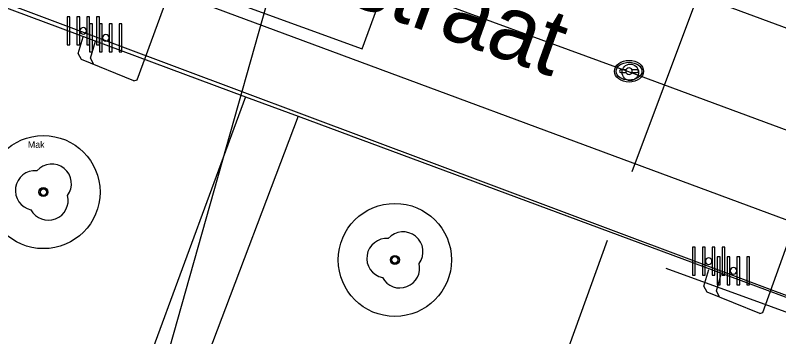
# Model space of a CAD drawing. Extents: x 192672 to 192910, y 446344 to 446512.
# Drawn here: x 192773.19 to 192796.29, y 446370.4 to 446380.14 of the extents above; entities that cross this region are included whole.
import ezdxf

# ---------------------------------------------------------------- set-up
doc = ezdxf.new("R2010")
doc.units = 0
for name, color, linetype in [('B-GV-GR-BOOM-S', 7, 'Continuous'), ('B-OI-KL-()_OVERIG_RIOOLVRIJVERVAL-S', 7, 'Continuous'), ('B-OI-KL-DATA_KABELBED-G', 7, 'Continuous'), ('B-OI-KL-ET_LS-G', 7, 'Continuous'), ('B-OI-RI-RIOOLVRIJVERVAL-G', 7, 'Continuous'), ('boom', 7, 'Continuous'), ('Default', 7, 'Continuous'), ('inspectie-   rioolput', 7, 'Continuous'), ('kant open verharding', 7, 'Continuous'), ('kant verharding', 7, 'Continuous'), ('kolk', 7, 'Continuous'), ('straatnaam', 7, 'Continuous'), ('TEKST', 7, 'Continuous'), ('verkeerseiland - berm', 7, 'Continuous')]:
    doc.layers.add(name, color=color, linetype=linetype)

# ---------------------------------------------------------------- blocks, each defined once
blk = doc.blocks.new('B-OI-KL-()_OVERIG_RIOOLVRIJVERVAL-S')
at = {"layer": 'Default'}
blk.add_circle((0, 0), 0.25, dxfattribs=at)

msp = doc.modelspace()

# ---------------------------------------------------------------- linework, layer by layer
at = {"layer": 'B-GV-GR-BOOM-S'}
for centre, radius in [((192774.039, 446374.78), 1.713), ((192774.039, 446374.78), 0.137), ((192784.676, 446372.725), 1.713), ((192784.676, 446372.725), 0.137)]:
    msp.add_circle(centre, radius, dxfattribs=at)
at = {"layer": 'B-OI-KL-DATA_KABELBED-G'}
msp.add_lwpolyline([(192744.469, 446391.186), (192762.819, 446384.291), (192799.152, 446370.668), (192816.75, 446364.01), (192817.485, 446363.735), (192812.909, 446351.776), (192812.803, 446351.499)], dxfattribs=at)
at = {"layer": 'B-OI-KL-ET_LS-G'}
for points in [[(192791.859, 446375.402), (192793.782, 446380.556), (192794.66, 446383.112), (192797.906, 446392.246), (192797.878, 446392.388)], [(192791.104, 446373.311), (192788.95, 446367.366), (192788.808, 446367.418), (192787.269, 446363.164)], [(192792.871, 446372.473), (192799.25, 446370.149), (192795.714, 446360.605), (192795.813, 446360.209), (192796.135, 446359.591), (192803.775, 446356.698), (192804.08, 446356.938)]]:
    msp.add_lwpolyline(points, dxfattribs=at)
at = {"layer": 'B-OI-RI-RIOOLVRIJVERVAL-G'}
for points in [[(192776.875, 446378.183), (192779.771, 446386.078)], [(192774.83, 446384.63), (192791.8, 446378.41)], [(192781.29, 446382.235), (192776.629, 446365.694)], [(192776.777, 446378.148), (192775.19, 446378.796), (192775.091, 446378.977), (192775.238, 446379.489)], [(192775.465, 446378.836), (192775.612, 446379.348)], [(192795.815, 446371.133), (192798.748, 446379.298)], [(192775.563, 446378.644), (192775.465, 446378.836)], [(192791.8, 446378.41), (192808.75, 446372.13)], [(192776.777, 446378.148), (192776.875, 446378.183)], [(192795.717, 446371.098), (192794.13, 446371.746), (192794.03, 446371.926), (192794.178, 446372.439)], [(192794.405, 446371.786), (192794.552, 446372.298)], [(192794.503, 446371.593), (192794.405, 446371.786)], [(192795.717, 446371.098), (192795.815, 446371.133)]]:
    msp.add_lwpolyline(points, dxfattribs=at)
at = {"layer": 'boom'}
for centre in [(192774.039, 446374.78), (192784.676, 446372.725)]:
    msp.add_circle(centre, 0.1, dxfattribs=at)
for centre, radius, start, end in [((192774.289, 446375.03), 0.6, 323.5446, 138.4658), ((192773.789, 446374.83), 0.6, 85.137, 257.7544), ((192774.039, 446374.78), 0.1, 0, 180), ((192774.189, 446374.53), 0.6, 208.5058, 13.8356), ((192774.039, 446374.78), 0.1, 180, 0), ((192784.926, 446372.975), 0.6, 323.5446, 138.4658), ((192784.426, 446372.775), 0.6, 85.137, 257.7544), ((192784.676, 446372.725), 0.1, 0, 180), ((192784.826, 446372.475), 0.6, 208.5058, 13.8356), ((192784.676, 446372.725), 0.1, 180, 0)]:
    msp.add_arc(centre, radius, start, end, dxfattribs=at)
at = {"layer": 'inspectie-   rioolput'}
for p, q in [((192791.669, 446378.48), (192791.512, 446378.48)), ((192791.512, 446378.405), (192791.669, 446378.405)), ((192792.012, 446378.48), (192791.855, 446378.48)), ((192791.855, 446378.405), (192792.012, 446378.405))]:
    msp.add_line(p, q, dxfattribs=at)
for centre, radius, start, end in [((192791.512, 446378.442), 0.0375, 90, 270), ((192791.762, 446378.442), 0.1, 0, 180), ((192791.762, 446378.442), 0.1, 157.9757, 180), ((192791.762, 446378.442), 0.1, 180, 202.0243), ((192791.762, 446378.442), 0.1, 180, 0), ((192791.762, 446378.442), 0.1, 0, 22.0243), ((192791.762, 446378.442), 0.1, 337.9757, 0), ((192792.012, 446378.442), 0.0375, 270, 90)]:
    msp.add_arc(centre, radius, start, end, dxfattribs=at)
for major_axis, ratio in [((-0.442, 0), 0.73911), ((-0.392, 0), 0.689655)]:
    msp.add_ellipse((192791.762, 446378.442), major_axis=major_axis, ratio=ratio, dxfattribs=at)
at = {"layer": 'kant open verharding'}
msp.add_lwpolyline([(192785.316, 446383.588), (192781.705, 446384.906), (192780.074, 446380.436), (192783.685, 446379.118), (192785.316, 446383.588)], dxfattribs=at)
at = {"layer": 'kant verharding'}
for p, q in [((192753.133, 446395.89), (192813.567, 446373.412)), ((192751.186, 446390.775), (192811.557, 446368.364)), ((192780.156, 446377.668), (192781.749, 446377.077))]:
    msp.add_line(p, q, dxfattribs=at)
at = {"layer": 'kolk'}
for points in [[(192774.842, 446379.663), (192774.842, 446380.088), (192774.757, 446380.088), (192774.757, 446379.663), (192774.757, 446379.238), (192774.842, 446379.238)], [(192775.14, 446379.663), (192775.14, 446380.088), (192775.055, 446380.088), (192775.055, 446379.663), (192775.055, 446379.238), (192775.14, 446379.238)], [(192775.437, 446379.663), (192775.437, 446380.088), (192775.352, 446380.088), (192775.352, 446379.663), (192775.352, 446379.238), (192775.437, 446379.238)], [(192775.735, 446379.663), (192775.735, 446380.088), (192775.65, 446380.088), (192775.65, 446379.663), (192775.65, 446379.238), (192775.735, 446379.238)], [(192775.521, 446379.454), (192775.521, 446379.879), (192775.436, 446379.879), (192775.436, 446379.454), (192775.436, 446379.029), (192775.521, 446379.029)], [(192775.819, 446379.454), (192775.819, 446379.879), (192775.734, 446379.879), (192775.734, 446379.454), (192775.734, 446379.029), (192775.819, 446379.029)], [(192776.116, 446379.454), (192776.116, 446379.879), (192776.031, 446379.879), (192776.031, 446379.454), (192776.031, 446379.029), (192776.116, 446379.029)], [(192776.414, 446379.454), (192776.414, 446379.879), (192776.329, 446379.879), (192776.329, 446379.454), (192776.329, 446379.029), (192776.414, 446379.029)], [(192793.768, 446372.686), (192793.768, 446373.111), (192793.683, 446373.111), (192793.683, 446372.686), (192793.683, 446372.261), (192793.768, 446372.261)], [(192794.066, 446372.686), (192794.066, 446373.111), (192793.981, 446373.111), (192793.981, 446372.686), (192793.981, 446372.261), (192794.066, 446372.261)], [(192794.363, 446372.686), (192794.363, 446373.111), (192794.278, 446373.111), (192794.278, 446372.686), (192794.278, 446372.261), (192794.363, 446372.261)], [(192794.661, 446372.686), (192794.661, 446373.111), (192794.576, 446373.111), (192794.576, 446372.686), (192794.576, 446372.261), (192794.661, 446372.261)], [(192794.518, 446372.391), (192794.518, 446372.816), (192794.433, 446372.816), (192794.433, 446372.391), (192794.433, 446371.966), (192794.518, 446371.966)], [(192794.816, 446372.391), (192794.816, 446372.816), (192794.731, 446372.816), (192794.731, 446372.391), (192794.731, 446371.966), (192794.816, 446371.966)], [(192795.113, 446372.391), (192795.113, 446372.816), (192795.028, 446372.816), (192795.028, 446372.391), (192795.028, 446371.966), (192795.113, 446371.966)], [(192795.411, 446372.391), (192795.411, 446372.816), (192795.326, 446372.816), (192795.326, 446372.391), (192795.326, 446371.966), (192795.411, 446371.966)]]:
    msp.add_lwpolyline(points, close=True, dxfattribs=at)
for centre, start, end in [((192775.246, 446379.663), 0, 180), ((192775.246, 446379.663), 180, 0), ((192775.925, 446379.454), 0, 180), ((192775.925, 446379.454), 180, 0), ((192794.172, 446372.686), 0, 180), ((192794.172, 446372.686), 180, 0), ((192794.922, 446372.391), 0, 180), ((192794.922, 446372.391), 180, 0)]:
    msp.add_arc(centre, 0.1, start, end, dxfattribs=at)
at = {"layer": 'verkeerseiland - berm'}
for p, q in [((192762.674, 446384.166), (192780.156, 446377.668)), ((192780.156, 446377.668), (192776.611, 446368.02)), ((192781.749, 446377.077), (192778.115, 446367.463)), ((192781.749, 446377.077), (192799.123, 446370.623))]:
    msp.add_line(p, q, dxfattribs=at)

# ---------------------------------------------------------------- block references
at = {"layer": 'B-OI-KL-()_OVERIG_RIOOLVRIJVERVAL-S'}
msp.add_blockref('B-OI-KL-()_OVERIG_RIOOLVRIJVERVAL-S', (192791.8, 446378.41), dxfattribs=at)

# ---------------------------------------------------------------- texts
at = {"layer": 'straatnaam'}
msp.add_text('Fokke Noordhoffstraat', height=2, rotation=340.2, dxfattribs=at).set_placement((192764.533, 446387.236))
at = {"layer": 'TEKST'}
msp.add_text('Mak', height=0.2, dxfattribs=at).set_placement((192773.569, 446376.121))

doc.saveas('drawing.dxf')
